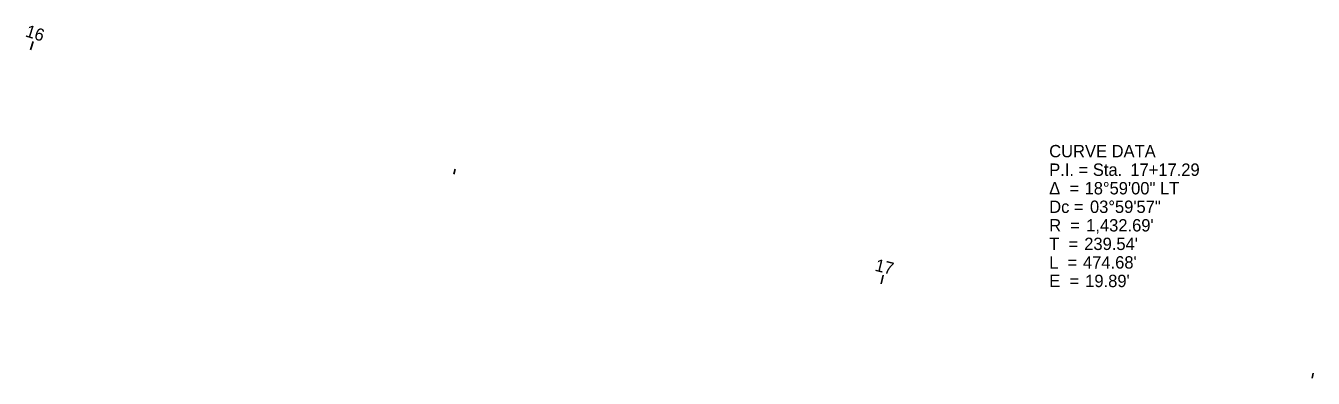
# Model space of a CAD drawing. Extents: x 2273904 to 2275373, y 654575 to 654883.
# Drawn here: x 2274111.7 to 2274257.6, y 654739.4 to 654779.3 of the extents above; entities that cross this region are included whole.
import ezdxf

# ---------------------------------------------------------------- set-up
doc = ezdxf.new("R2010")
doc.units = 0
for name, color, linetype in [('DR_P_Headwall', 7, 'Continuous'), ('DR_P_Storm_Sewer', 7, 'Continuous'), ('GE_X_Alignment_1000_Stations', 7, 'Continuous'), ('GE_X_Alignment_500_Stations', 7, 'Continuous'), ('PV_P_EOP', 7, 'Continuous')]:
    doc.layers.add(name, color=color, linetype=linetype)

msp = doc.modelspace()

# ---------------------------------------------------------------- linework, layer by layer
at = {"layer": 'DR_P_Storm_Sewer'}
for p, q in [((2274112.25, 654776.55), (2274112.43, 654777.12)), ((2274208.65, 654750.06), (2274208.79, 654750.64))]:
    msp.add_line(p, q, dxfattribs=at)
at = {"layer": 'GE_X_Alignment_1000_Stations'}
for p, q in [((2274112.25, 654776.55), (2274112.54, 654777.5)), ((2274160.22, 654762.46), (2274160.38, 654763.04)), ((2274208.65, 654750.06), (2274208.89, 654751.03)), ((2274257.49, 654739.36), (2274257.61, 654739.95))]:
    msp.add_line(p, q, dxfattribs=at)

# ---------------------------------------------------------------- texts
at = {"layer": 'DR_P_Headwall'}
for s, p in [('CURVE DATA', (2274227.69, 654764.38)), ('P.I. = Sta. ', (2274227.69, 654762.28)), ('17+17.29', (2274236.88, 654762.28)), ('Δ  = ', (2274227.69, 654760.18)), ('18°59\'00" LT', (2274231.7, 654760.18)), ('Dc = ', (2274227.69, 654758.08)), ('03°59\'57"', (2274232.31, 654758.08)), ('R  = ', (2274227.69, 654755.98)), ("1,432.69'", (2274231.88, 654755.98)), ('T  = ', (2274227.69, 654753.88)), ("239.54'", (2274231.66, 654753.88)), ('L  = ', (2274227.69, 654751.78)), ("474.68'", (2274231.52, 654751.78)), ('E  = ', (2274227.69, 654749.68)), ("19.89'", (2274231.77, 654749.68))]:
    msp.add_text(s, height=1.4, dxfattribs=at).set_placement(p)
at = {"layer": 'GE_X_Alignment_1000_Stations'}
for s, rotation, p in [('16', 342.6396, (2274111.58, 654778.09)), ('17', 346.6388, (2274207.85, 654751.54))]:
    msp.add_text(s, height=1.4, rotation=rotation, dxfattribs=at).set_placement(p)
at = {"layer": 'GE_X_Alignment_500_Stations'}
for s, p in [('CURVE DATA', (2274227.69, 654764.38)), ('P.I. = Sta. ', (2274227.69, 654762.28)), ('17+17.29', (2274236.88, 654762.28)), ('Δ  = ', (2274227.69, 654760.18)), ('18°59\'00" LT', (2274231.7, 654760.18)), ('Dc = ', (2274227.69, 654758.08)), ('03°59\'57"', (2274232.31, 654758.08)), ('R  = ', (2274227.69, 654755.98)), ("1,432.69'", (2274231.88, 654755.98)), ('T  = ', (2274227.69, 654753.88)), ("239.54'", (2274231.66, 654753.88)), ('L  = ', (2274227.69, 654751.78)), ("474.68'", (2274231.52, 654751.78)), ('E  = ', (2274227.69, 654749.68)), ("19.89'", (2274231.77, 654749.68))]:
    msp.add_text(s, height=1.4, dxfattribs=at).set_placement(p)
at = {"layer": 'PV_P_EOP'}
for s, p in [('CURVE DATA', (2274227.69, 654764.38)), ('P.I. = Sta. ', (2274227.69, 654762.28)), ('17+17.29', (2274236.88, 654762.28)), ('Δ  = ', (2274227.69, 654760.18)), ('18°59\'00" LT', (2274231.7, 654760.18)), ('Dc = ', (2274227.69, 654758.08)), ('03°59\'57"', (2274232.31, 654758.08)), ('R  = ', (2274227.69, 654755.98)), ("1,432.69'", (2274231.88, 654755.98)), ('T  = ', (2274227.69, 654753.88)), ("239.54'", (2274231.66, 654753.88)), ('L  = ', (2274227.69, 654751.78)), ("474.68'", (2274231.52, 654751.78)), ('E  = ', (2274227.69, 654749.68)), ("19.89'", (2274231.77, 654749.68))]:
    msp.add_text(s, height=1.4, dxfattribs=at).set_placement(p)

doc.saveas('drawing.dxf')
